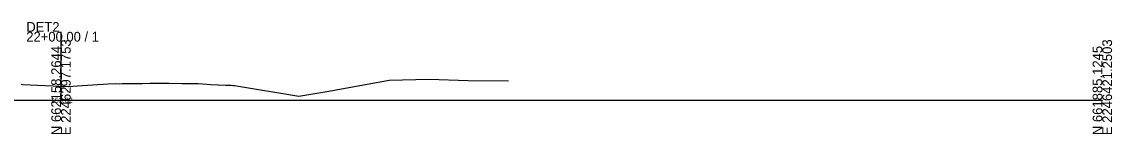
# Model space of a CAD drawing. Extents: x -26 to 603, y -10 to 9526.
# Drawn here: x 288.7 to 602.8, y 4990.3 to 5022.5 of the extents above; entities that cross this region are included whole.
import ezdxf

# ---------------------------------------------------------------- set-up
doc = ezdxf.new("R2010")
doc.units = 0
for name, color, linetype in [('Exist Cross Section Cell', 7, 'Continuous'), ('Exist XS Center Line Elevation Label', 7, 'Continuous'), ('Exist XS Ground Line', 7, 'Continuous')]:
    doc.layers.add(name, color=color, linetype=linetype)

msp = doc.modelspace()

# ---------------------------------------------------------------- linework, layer by layer
at = {"layer": 'Exist Cross Section Cell'}
for p, q in [((300, 5000), (300, 5019.64)), ((0, 5000), (300, 5000)), ((300, 5000), (600, 5000))]:
    msp.add_line(p, q, dxfattribs=at)
at = {"layer": 'Exist XS Ground Line'}
for p, q in [((288.52, 5004.66), (288.89, 5004.55)), ((288.89, 5004.55), (295.4, 5004.24)), ((295.4, 5004.24), (300, 5004.02)), ((302.02, 5003.93), (306.1, 5004.21)), ((306.1, 5004.21), (312.17, 5004.64)), ((312.17, 5004.64), (313.49, 5004.72)), ((313.49, 5004.72), (315.7, 5004.84)), ((315.7, 5004.84), (316.73, 5004.76)), ((316.73, 5004.76), (317.61, 5004.78)), ((317.61, 5004.78), (319.7, 5004.81)), ((319.7, 5004.81), (320.06, 5004.82)), ((320.06, 5004.82), (323.48, 5004.86)), ((323.48, 5004.86), (325.55, 5004.9)), ((325.55, 5004.9), (327.09, 5004.96)), ((327.09, 5004.96), (331.04, 5004.9)), ((331.04, 5004.9), (334.81, 5004.84)), ((334.81, 5004.84), (336.54, 5004.81)), ((336.54, 5004.81), (338.59, 5004.81)), ((338.59, 5004.81), (339.17, 5004.8)), ((339.17, 5004.8), (339.55, 5004.8)), ((339.55, 5004.8), (342.03, 5004.61)), ((342.03, 5004.61), (343.1, 5004.56)), ((343.1, 5004.56), (347.52, 5004.38)), ((347.52, 5004.38), (349.03, 5004.31)), ((349.03, 5004.31), (349.58, 5004.28)), ((349.58, 5004.28), (350, 5004.22)), ((350, 5004.22), (368.51, 5001.16)), ((377.14, 5002.58), (394.57, 5005.74)), ((394.57, 5005.74), (406.11, 5006.05)), ((406.11, 5006.05), (417.26, 5005.68)), ((417.26, 5005.68), (428.89, 5005.6)), ((300, 5004.02), (302.02, 5003.93)), ((368.51, 5001.16), (377.14, 5002.58))]:
    msp.add_line(p, q, dxfattribs=at)

# ---------------------------------------------------------------- texts
at = {"layer": 'Exist Cross Section Cell'}
for s, p in [('DET2', (290, 5019.64)), ('22+00.00 / 1', (290, 5016.84))]:
    msp.add_text(s, height=2.8, dxfattribs=at).set_placement(p)
for s, p in [('E 2246297.1753', (302.8, 4990)), ('E 2246421.2503', (602.8, 4990)), ('N 662158.2644', (300, 4990)), ('N 661885.1245', (600, 4990))]:
    msp.add_text(s, height=2.8, rotation=90, dxfattribs=at).set_placement(p)
at = {"layer": 'Exist XS Center Line Elevation Label'}
msp.add_text('153.02', height=1.5, dxfattribs=at).set_placement((297.02, 4999.27))

doc.saveas('drawing.dxf')
